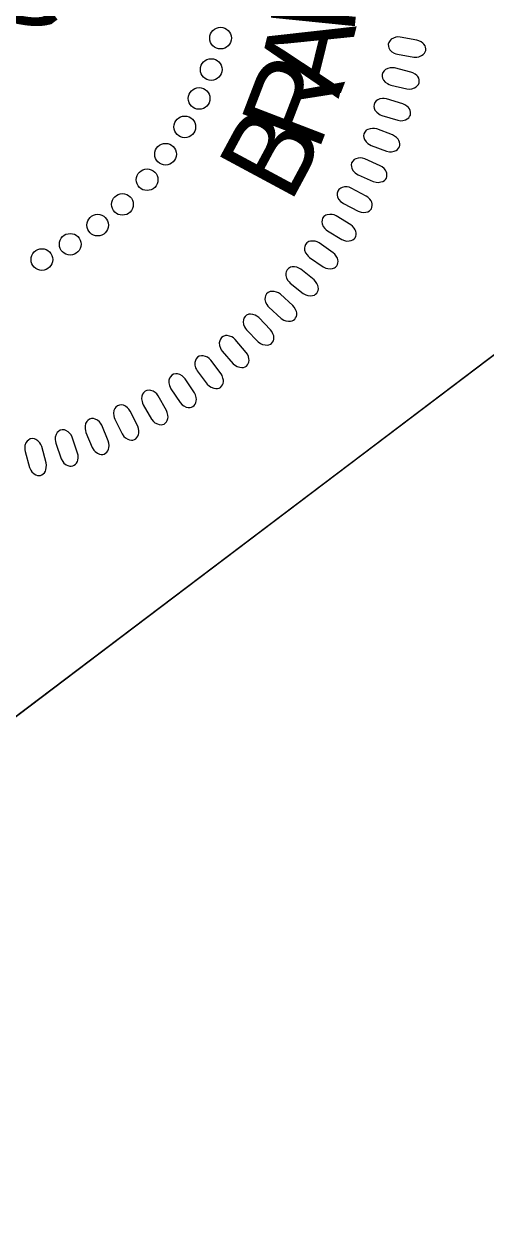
# Model space of a CAD drawing. Extents: x 475599 to 477488, y 499839 to 501843.
# Drawn here: x 475808.5 to 475842.6, y 501029.5 to 501118.9 of the extents above; entities that cross this region are included whole.
import ezdxf

# ---------------------------------------------------------------- set-up
doc = ezdxf.new("R2010")
doc.units = 0
for name, color, linetype in [('Sheet Layout Plan Border', 7, 'Continuous'), ('Sheet PE Seal Cell', 7, 'Continuous'), ('Sheet Plan CELL', 7, 'Continuous')]:
    doc.layers.add(name, color=color, linetype=linetype)

msp = doc.modelspace()

# ---------------------------------------------------------------- linework, layer by layer
at = {"layer": 'Sheet Layout Plan Border'}
msp.add_lwpolyline([(477369.485, 500619.343), (476565.061, 501682.05), (476503.293, 501631.072), (476482.512, 501623.318), (476353.406, 501551.571), (476353.406, 501551.571), (475928.123, 501315.23), (475798.165, 501243.009), (475886.058, 501126.892), (475780.946, 501047.326), (475875.923, 500921.851), (475842.657, 500896.671), (476532.299, 499985.628)], close=True, dxfattribs=at)
at = {"layer": 'Sheet PE Seal Cell'}
for points in [[(475836.093, 501116.693), (475837.303, 501116.487), (475837.525, 501116.486), (475837.671, 501116.514), (475837.858, 501116.596), (475837.982, 501116.674), (475838.08, 501116.771), (475838.137, 501116.868), (475838.175, 501116.975), (475838.174, 501117.089), (475838.165, 501117.212), (475838.124, 501117.324), (475838.043, 501117.445), (475837.975, 501117.517), (475837.838, 501117.609), (475837.671, 501117.698), (475837.518, 501117.747), (475836.281, 501117.966), (475836.109, 501117.972), (475835.964, 501117.951), (475835.792, 501117.89), (475835.635, 501117.803), (475835.541, 501117.721), (475835.455, 501117.576), (475835.41, 501117.432), (475835.424, 501117.278), (475835.456, 501117.166), (475835.533, 501117.024), (475835.68, 501116.878), (475835.846, 501116.781), (475835.968, 501116.73)], [(475835.593, 501114.421), (475836.787, 501114.139), (475837.009, 501114.125), (475837.157, 501114.143), (475837.348, 501114.213), (475837.477, 501114.282), (475837.58, 501114.373), (475837.643, 501114.466), (475837.688, 501114.571), (475837.694, 501114.684), (475837.693, 501114.808), (475837.659, 501114.923), (475837.586, 501115.048), (475837.522, 501115.124), (475837.392, 501115.225), (475837.231, 501115.324), (475837.081, 501115.382), (475835.859, 501115.679), (475835.69, 501115.696), (475835.543, 501115.684), (475835.368, 501115.634), (475835.205, 501115.557), (475835.106, 501115.481), (475835.011, 501115.342), (475834.958, 501115.2), (475834.962, 501115.046), (475834.987, 501114.933), (475835.054, 501114.786), (475835.191, 501114.631), (475835.351, 501114.523), (475835.47, 501114.465)], [(475834.94, 501112.166), (475836.114, 501111.81), (475836.334, 501111.782), (475836.484, 501111.79), (475836.678, 501111.849), (475836.812, 501111.91), (475836.92, 501111.994), (475836.989, 501112.082), (475837.041, 501112.185), (475837.054, 501112.297), (475837.06, 501112.421), (475837.034, 501112.538), (475836.968, 501112.667), (475836.909, 501112.748), (475836.786, 501112.856), (475836.632, 501112.965), (475836.486, 501113.033), (475835.286, 501113.405), (475835.116, 501113.433), (475834.97, 501113.43), (475834.791, 501113.391), (475834.625, 501113.324), (475834.52, 501113.255), (475834.417, 501113.122), (475834.355, 501112.984), (475834.35, 501112.83), (475834.367, 501112.715), (475834.425, 501112.564), (475834.553, 501112.401), (475834.705, 501112.284), (475834.82, 501112.218)], [(475834.135, 501109.957), (475835.285, 501109.527), (475835.503, 501109.485), (475835.652, 501109.485), (475835.851, 501109.531), (475835.987, 501109.583), (475836.102, 501109.66), (475836.175, 501109.745), (475836.233, 501109.843), (475836.253, 501109.955), (475836.268, 501110.077), (475836.248, 501110.196), (475836.191, 501110.329), (475836.138, 501110.413), (475836.021, 501110.529), (475835.874, 501110.647), (475835.733, 501110.724), (475834.558, 501111.171), (475834.392, 501111.21), (475834.244, 501111.216), (475834.064, 501111.188), (475833.894, 501111.132), (475833.785, 501111.069), (475833.674, 501110.943), (475833.603, 501110.81), (475833.588, 501110.656), (475833.598, 501110.541), (475833.647, 501110.386), (475833.764, 501110.215), (475833.909, 501110.089), (475834.02, 501110.016)], [(475833.179, 501107.782), (475834.3, 501107.281), (475834.514, 501107.226), (475834.664, 501107.217), (475834.864, 501107.249), (475835.005, 501107.294), (475835.122, 501107.364), (475835.202, 501107.443), (475835.266, 501107.537), (475835.293, 501107.647), (475835.314, 501107.769), (475835.303, 501107.889), (475835.254, 501108.025), (475835.206, 501108.112), (475835.097, 501108.235), (475834.957, 501108.362), (475834.821, 501108.449), (475833.677, 501108.968), (475833.513, 501109.017), (475833.367, 501109.032), (475833.185, 501109.016), (475833.012, 501108.971), (475832.899, 501108.915), (475832.781, 501108.796), (475832.701, 501108.667), (475832.677, 501108.514), (475832.679, 501108.399), (475832.718, 501108.242), (475832.825, 501108.064), (475832.961, 501107.929), (475833.067, 501107.849)], [(475832.098, 501105.65), (475833.185, 501105.08), (475833.396, 501105.011), (475833.544, 501104.992), (475833.746, 501105.014), (475833.889, 501105.048), (475834.012, 501105.111), (475834.095, 501105.185), (475834.165, 501105.275), (475834.199, 501105.383), (475834.228, 501105.503), (475834.224, 501105.624), (475834.184, 501105.762), (475834.142, 501105.853), (475834.041, 501105.982), (475833.909, 501106.118), (475833.779, 501106.212), (475832.669, 501106.803), (475832.508, 501106.862), (475832.364, 501106.887), (475832.182, 501106.882), (475832.006, 501106.848), (475831.89, 501106.798), (475831.764, 501106.687), (475831.676, 501106.564), (475831.643, 501106.413), (475831.638, 501106.297), (475831.667, 501106.138), (475831.762, 501105.954), (475831.889, 501105.81), (475831.99, 501105.724)], [(475830.919, 501103.63), (475831.967, 501102.992), (475832.175, 501102.91), (475832.321, 501102.882), (475832.524, 501102.89), (475832.669, 501102.916), (475832.795, 501102.971), (475832.883, 501103.039), (475832.959, 501103.125), (475833, 501103.231), (475833.036, 501103.349), (475833.04, 501103.469), (475833.008, 501103.61), (475832.972, 501103.703), (475832.878, 501103.838), (475832.756, 501103.982), (475832.632, 501104.084), (475831.562, 501104.744), (475831.405, 501104.813), (475831.263, 501104.847), (475831.08, 501104.853), (475830.902, 501104.83), (475830.783, 501104.788), (475830.651, 501104.685), (475830.556, 501104.567), (475830.513, 501104.42), (475830.501, 501104.304), (475830.52, 501104.143), (475830.603, 501103.954), (475830.721, 501103.802), (475830.817, 501103.71)], [(475829.594, 501101.675), (475830.6, 501100.973), (475830.801, 501100.878), (475830.945, 501100.84), (475831.149, 501100.836), (475831.295, 501100.853), (475831.424, 501100.899), (475831.516, 501100.962), (475831.597, 501101.043), (475831.644, 501101.146), (475831.688, 501101.261), (475831.699, 501101.381), (475831.677, 501101.524), (475831.647, 501101.619), (475831.562, 501101.76), (475831.449, 501101.911), (475831.331, 501102.021), (475830.304, 501102.746), (475830.152, 501102.824), (475830.012, 501102.868), (475829.831, 501102.885), (475829.652, 501102.873), (475829.53, 501102.839), (475829.392, 501102.745), (475829.29, 501102.633), (475829.237, 501102.488), (475829.218, 501102.374), (475829.227, 501102.213), (475829.298, 501102.018), (475829.406, 501101.86), (475829.496, 501101.761)], [(475828.167, 501099.775), (475829.127, 501099.011), (475829.322, 501098.904), (475829.464, 501098.858), (475829.667, 501098.84), (475829.813, 501098.848), (475829.945, 501098.886), (475830.041, 501098.943), (475830.127, 501099.019), (475830.181, 501099.118), (475830.232, 501099.231), (475830.251, 501099.35), (475830.237, 501099.494), (475830.212, 501099.591), (475830.137, 501099.736), (475830.034, 501099.895), (475829.923, 501100.012), (475828.944, 501100.8), (475828.797, 501100.888), (475828.66, 501100.939), (475828.479, 501100.968), (475828.3, 501100.968), (475828.178, 501100.941), (475828.033, 501100.856), (475827.924, 501100.751), (475827.863, 501100.609), (475827.837, 501100.496), (475827.835, 501100.335), (475827.894, 501100.136), (475827.992, 501099.971), (475828.075, 501099.867)], [(475826.59, 501097.98), (475827.5, 501097.157), (475827.688, 501097.038), (475827.826, 501096.983), (475828.028, 501096.952), (475828.174, 501096.951), (475828.309, 501096.981), (475828.408, 501097.032), (475828.498, 501097.102), (475828.558, 501097.198), (475828.616, 501097.307), (475828.643, 501097.425), (475828.638, 501097.569), (475828.619, 501097.667), (475828.554, 501097.818), (475828.46, 501097.982), (475828.357, 501098.106), (475827.43, 501098.954), (475827.289, 501099.05), (475827.155, 501099.111), (475826.977, 501099.151), (475826.798, 501099.162), (475826.673, 501099.143), (475826.524, 501099.067), (475826.409, 501098.969), (475826.338, 501098.832), (475826.305, 501098.72), (475826.294, 501098.559), (475826.34, 501098.357), (475826.428, 501098.186), (475826.504, 501098.078)], [(475824.937, 501096.31), (475825.794, 501095.432), (475825.974, 501095.302), (475826.109, 501095.238), (475826.307, 501095.195), (475826.454, 501095.184), (475826.59, 501095.206), (475826.692, 501095.25), (475826.787, 501095.315), (475826.853, 501095.407), (475826.917, 501095.512), (475826.951, 501095.628), (475826.956, 501095.772), (475826.943, 501095.872), (475826.887, 501096.025), (475826.804, 501096.195), (475826.709, 501096.325), (475825.836, 501097.23), (475825.702, 501097.335), (475825.572, 501097.404), (475825.397, 501097.456), (475825.219, 501097.477), (475825.094, 501097.467), (475824.939, 501097.4), (475824.819, 501097.309), (475824.739, 501097.176), (475824.699, 501097.067), (475824.678, 501096.907), (475824.711, 501096.703), (475824.788, 501096.527), (475824.857, 501096.414)], [(475823.138, 501094.742), (475823.938, 501093.812), (475824.109, 501093.67), (475824.24, 501093.598), (475824.436, 501093.543), (475824.581, 501093.522), (475824.718, 501093.535), (475824.823, 501093.573), (475824.921, 501093.632), (475824.993, 501093.72), (475825.064, 501093.821), (475825.105, 501093.934), (475825.119, 501094.078), (475825.112, 501094.178), (475825.066, 501094.335), (475824.994, 501094.51), (475824.907, 501094.645), (475824.093, 501095.603), (475823.965, 501095.717), (475823.84, 501095.793), (475823.668, 501095.855), (475823.492, 501095.888), (475823.367, 501095.886), (475823.208, 501095.829), (475823.082, 501095.746), (475822.995, 501095.618), (475822.948, 501095.512), (475822.917, 501095.354), (475822.937, 501095.148), (475823.003, 501094.967), (475823.065, 501094.849)], [(475821.29, 501093.277), (475822.03, 501092.299), (475822.192, 501092.147), (475822.318, 501092.066), (475822.509, 501091.999), (475822.653, 501091.97), (475822.791, 501091.975), (475822.898, 501092.006), (475823, 501092.057), (475823.077, 501092.141), (475823.154, 501092.237), (475823.202, 501092.347), (475823.225, 501092.49), (475823.225, 501092.59), (475823.188, 501092.75), (475823.127, 501092.929), (475823.049, 501093.07), (475822.297, 501094.077), (475822.177, 501094.198), (475822.057, 501094.283), (475821.889, 501094.355), (475821.715, 501094.399), (475821.59, 501094.405), (475821.428, 501094.358), (475821.297, 501094.283), (475821.202, 501094.161), (475821.149, 501094.058), (475821.107, 501093.902), (475821.114, 501093.695), (475821.169, 501093.511), (475821.223, 501093.389)], [(475819.337, 501091.962), (475820.014, 501090.939), (475820.166, 501090.777), (475820.287, 501090.689), (475820.474, 501090.609), (475820.616, 501090.571), (475820.753, 501090.567), (475820.862, 501090.592), (475820.967, 501090.637), (475821.049, 501090.716), (475821.133, 501090.807), (475821.187, 501090.914), (475821.219, 501091.055), (475821.225, 501091.155), (475821.199, 501091.317), (475821.149, 501091.499), (475821.08, 501091.645), (475820.392, 501092.697), (475820.28, 501092.826), (475820.166, 501092.917), (475820.002, 501093.001), (475819.832, 501093.055), (475819.707, 501093.068), (475819.543, 501093.031), (475819.407, 501092.965), (475819.305, 501092.85), (475819.245, 501092.75), (475819.194, 501092.597), (475819.188, 501092.39), (475819.231, 501092.203), (475819.278, 501092.078)], [(475817.295, 501090.776), (475817.907, 501089.713), (475818.048, 501089.541), (475818.163, 501089.445), (475818.345, 501089.355), (475818.484, 501089.308), (475818.621, 501089.295), (475818.731, 501089.312), (475818.839, 501089.351), (475818.926, 501089.424), (475819.015, 501089.51), (475819.076, 501089.614), (475819.116, 501089.753), (475819.128, 501089.852), (475819.112, 501090.015), (475819.075, 501090.2), (475819.015, 501090.35), (475818.395, 501091.443), (475818.29, 501091.579), (475818.182, 501091.677), (475818.025, 501091.771), (475817.858, 501091.836), (475817.734, 501091.856), (475817.568, 501091.83), (475817.428, 501091.773), (475817.319, 501091.664), (475817.253, 501091.568), (475817.192, 501091.419), (475817.174, 501091.212), (475817.205, 501091.022), (475817.243, 501090.896)], [(475815.196, 501089.714), (475815.74, 501088.615), (475815.87, 501088.435), (475815.979, 501088.332), (475816.155, 501088.23), (475816.29, 501088.174), (475816.427, 501088.153), (475816.538, 501088.163), (475816.647, 501088.195), (475816.738, 501088.263), (475816.833, 501088.343), (475816.9, 501088.442), (475816.949, 501088.578), (475816.968, 501088.676), (475816.962, 501088.841), (475816.936, 501089.028), (475816.886, 501089.181), (475816.335, 501090.311), (475816.24, 501090.453), (475816.137, 501090.558), (475815.987, 501090.661), (475815.825, 501090.737), (475815.702, 501090.765), (475815.535, 501090.749), (475815.392, 501090.701), (475815.275, 501090.599), (475815.204, 501090.508), (475815.134, 501090.362), (475815.101, 501090.157), (475815.121, 501089.966), (475815.152, 501089.837)], [(475813.057, 501088.736), (475813.531, 501087.605), (475813.65, 501087.417), (475813.752, 501087.308), (475813.921, 501087.195), (475814.053, 501087.131), (475814.187, 501087.1), (475814.299, 501087.105), (475814.41, 501087.129), (475814.506, 501087.19), (475814.605, 501087.265), (475814.678, 501087.36), (475814.736, 501087.492), (475814.761, 501087.589), (475814.765, 501087.754), (475814.75, 501087.942), (475814.71, 501088.098), (475814.232, 501089.26), (475814.145, 501089.408), (475814.05, 501089.519), (475813.906, 501089.631), (475813.749, 501089.717), (475813.628, 501089.753), (475813.46, 501089.748), (475813.315, 501089.709), (475813.192, 501089.614), (475813.115, 501089.528), (475813.036, 501089.387), (475812.991, 501089.184), (475812.998, 501088.993), (475813.021, 501088.861)], [(475808.559, 501087.314), (475808.887, 501086.132), (475808.982, 501085.93), (475809.069, 501085.809), (475809.223, 501085.676), (475809.346, 501085.596), (475809.475, 501085.55), (475809.587, 501085.54), (475809.701, 501085.55), (475809.803, 501085.599), (475809.91, 501085.66), (475809.995, 501085.745), (475810.069, 501085.869), (475810.106, 501085.963), (475810.13, 501086.125), (475810.139, 501086.314), (475810.119, 501086.473), (475809.79, 501087.686), (475809.723, 501087.843), (475809.642, 501087.966), (475809.514, 501088.096), (475809.368, 501088.2), (475809.253, 501088.251), (475809.086, 501088.268), (475808.937, 501088.246), (475808.804, 501088.168), (475808.716, 501088.092), (475808.62, 501087.962), (475808.55, 501087.767), (475808.534, 501087.575), (475808.539, 501087.442)], [(475810.833, 501087.937), (475811.235, 501086.778), (475811.342, 501086.583), (475811.437, 501086.467), (475811.599, 501086.344), (475811.727, 501086.272), (475811.859, 501086.233), (475811.97, 501086.23), (475812.083, 501086.248), (475812.182, 501086.304), (475812.285, 501086.371), (475812.364, 501086.461), (475812.431, 501086.59), (475812.461, 501086.685), (475812.476, 501086.849), (475812.474, 501087.037), (475812.443, 501087.196), (475812.039, 501088.386), (475811.962, 501088.539), (475811.873, 501088.656), (475811.737, 501088.777), (475811.585, 501088.872), (475811.467, 501088.917), (475811.299, 501088.922), (475811.152, 501088.891), (475811.023, 501088.804), (475810.941, 501088.723), (475810.853, 501088.588), (475810.796, 501088.388), (475810.791, 501088.196), (475810.805, 501088.064)]]:
    msp.add_lwpolyline(points, close=True, dxfattribs=at)
for centre in [(475823.011, 501117.887), (475822.319, 501115.566), (475821.427, 501113.425), (475820.367, 501111.325), (475818.949, 501109.304), (475817.578, 501107.419), (475815.761, 501105.595), (475813.927, 501104.057), (475811.896, 501102.641), (475809.805, 501101.509)]:
    msp.add_circle(centre, 0.801, dxfattribs=at)
at = {"layer": 'Sheet Plan CELL'}
for points in [[(477369.494, 500619.368), (476532.299, 499985.628), (475747.678, 501022.142), (475867.321, 501112.709), (475746.601, 501272.214), (476464.153, 501815.359)], [(475777.638, 501044.809), (475717.254, 501124.582), (475806.965, 501192.488), (475867.321, 501112.709)]]:
    msp.add_lwpolyline(points, close=True, dxfattribs=at)

# ---------------------------------------------------------------- texts
at = {"layer": 'Sheet PE Seal Cell'}
for s, height, rotation, p in [('29470', 6.2363, 127.105, (475811.214, 501118.929)), ('N', 6.236, 84.21638, (475832.869, 501118.092)), ('A', 6.236, 76.1052, (475831.739, 501113.374)), ('R', 6.236, 68.98836, (475830.207, 501109.403)), ('B', 6.236, 61.71333, (475828.146, 501105.571))]:
    msp.add_text(s, height=height, rotation=rotation, dxfattribs=at).set_placement(p)

doc.saveas('drawing.dxf')
